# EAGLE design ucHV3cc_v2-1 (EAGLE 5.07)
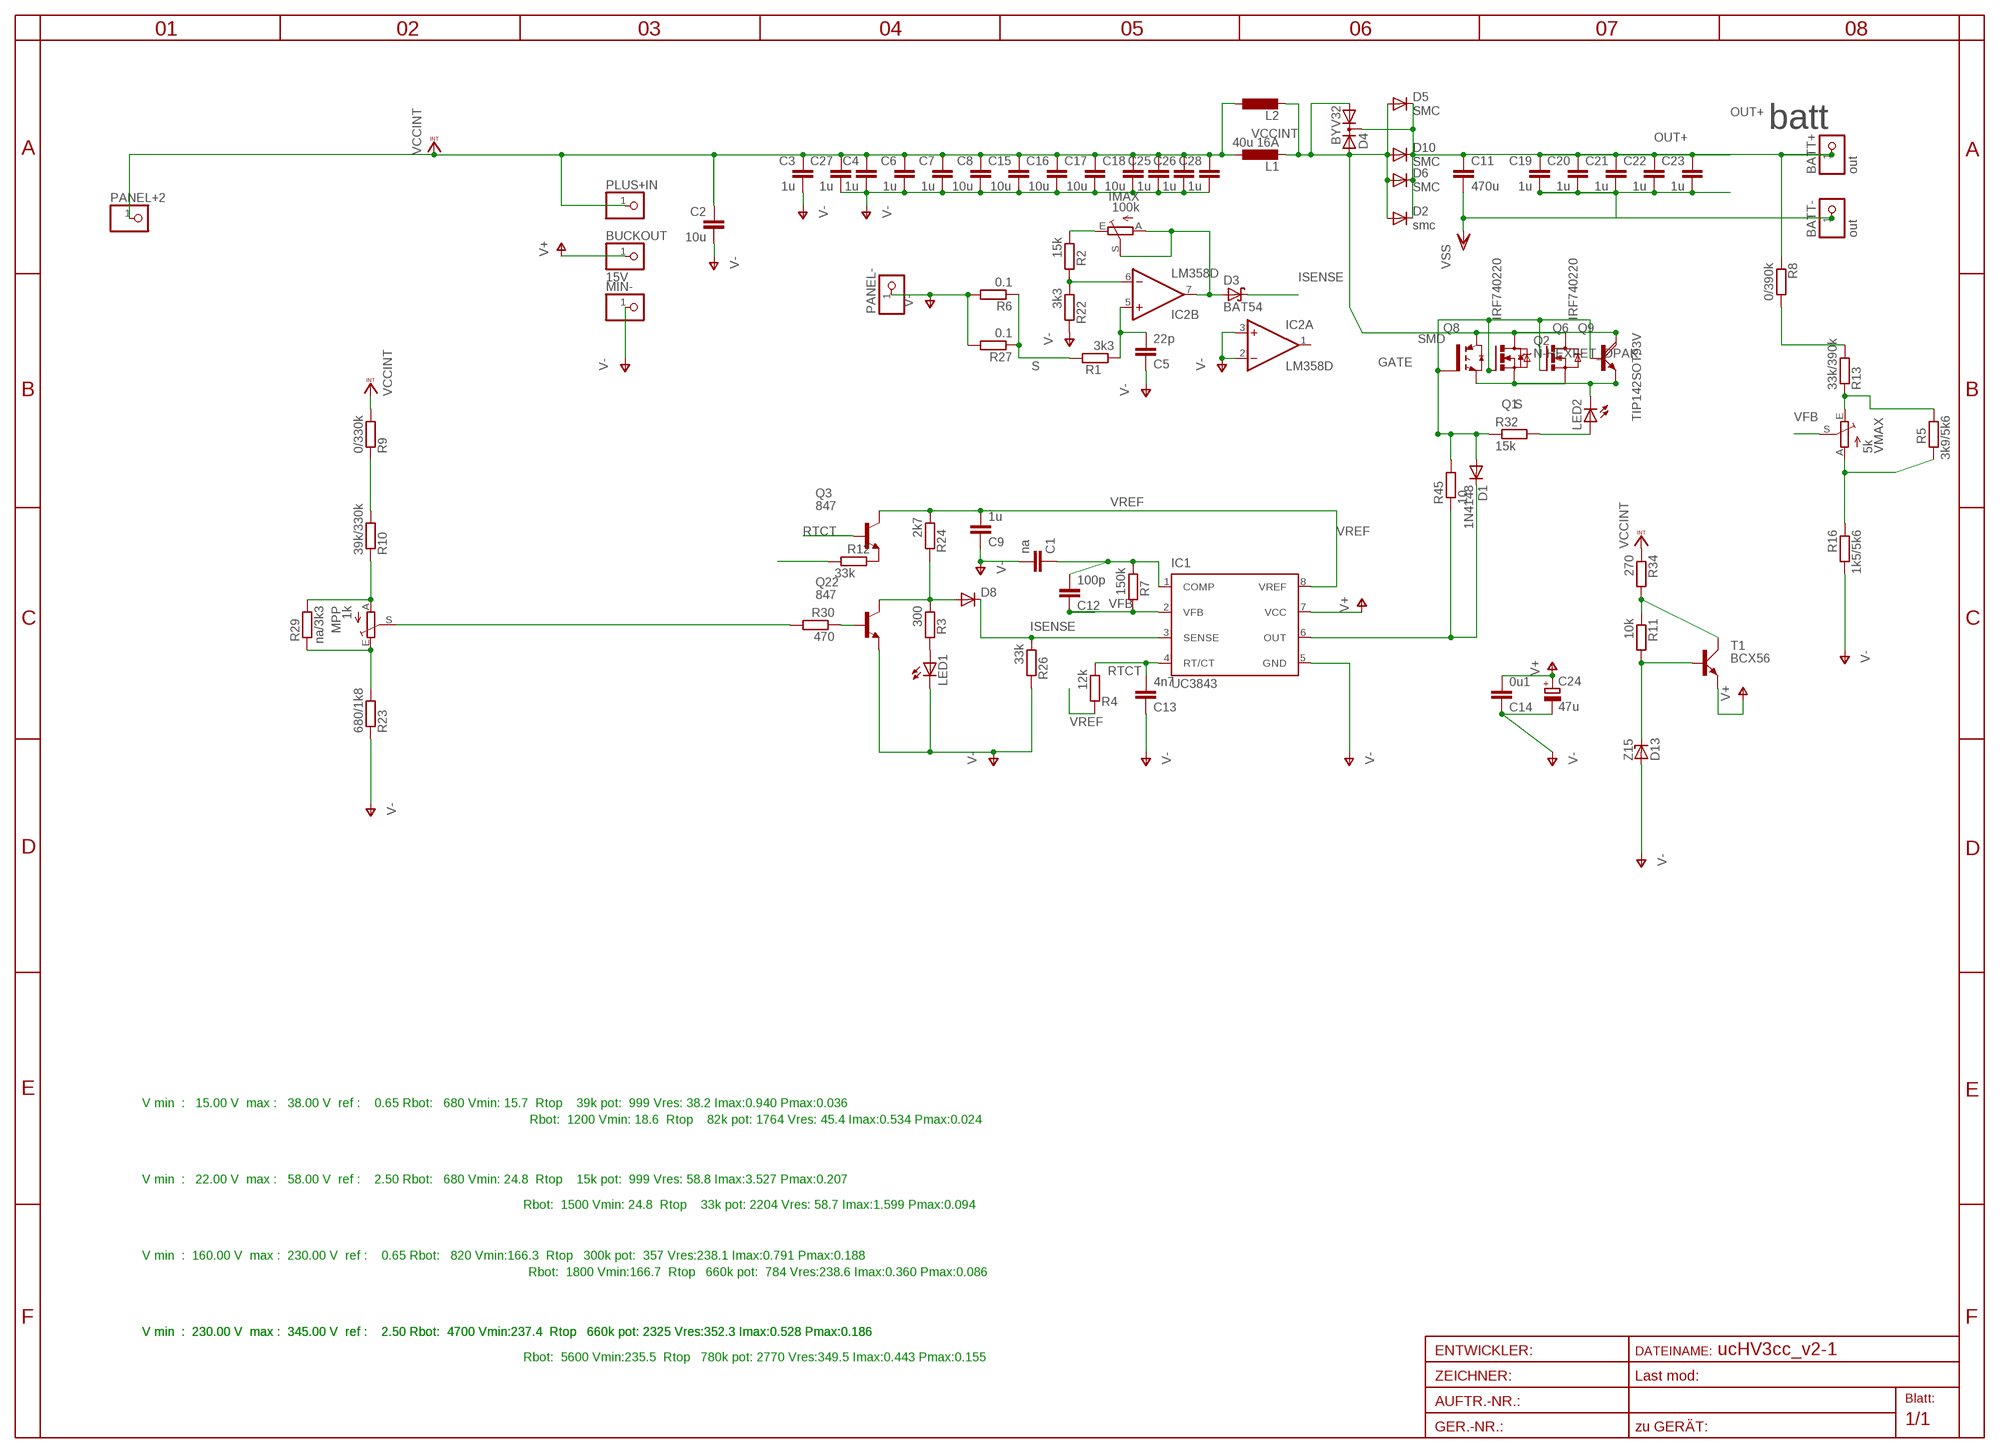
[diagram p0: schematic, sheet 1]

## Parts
BATT+  out  PINHD-1X12MM2  [1X2MM2]
BATT-  out  PINHD-1X12MM2  [1X2MM2]
BUCKOUT  15V  PINHD-1X11MM0  [1X1MM0]
C1  na  C-EUC0805  [C0805]
C2  10u  C-EUC058MLCC  [C058-020X040]
C3  1u  C-EUC058MLCC  [C058-020X040]
C4  1u  C-EUC058MLCC  [C058-020X040]
C5  22p  C-EUC0805  [C0805]
C6  1u  C-EUC058MLCC  [C058-020X040]
C7  1u  C-EUC058MLCC  [C058-020X040]
C8  10u  C-EUC058MLCC  [C058-020X040]
C9  1u  C-EUC1206  [C1206]
C11  470u  C-EU075-052X106  [C075-052X106]
C12  100p  C-EUC0805  [C0805]
C13  4n7  C-EUC0805  [C0805]
C14  0u1  C-EUC1206  [C1206]
C15  10u  C-EUC058MLCC  [C058-020X040]
C16  10u  C-EUC058MLCC  [C058-020X040]
C17  10u  C-EUC058MLCC  [C058-020X040]
C18  10u  C-EUC058MLCC  [C058-020X040]
C19  1u  C-EUC1206  [C1206]
C20  1u  C-EUC1206  [C1206]
C21  1u  C-EUC1206  [C1206]
C22  1u  C-EUC1206  [C1206]
C23  1u  C-EUC1206  [C1206]
C24  47u  CPOL-EUSANYO_SMD_C6  [SANYO-OSCON_SMD_C6]
C25  1u  C-EUC058MLCC  [C058-020X040]
C26  1u  C-EUC058MLCC  [C058-020X040]
C27  1u  C-EUC058MLCC  [C058-020X040]
C28  1u  C-EUC058MLCC  [C058-020X040]
D1  1N4148  DIODE-MINIMELF  [MINIMELF]
D2  smc  DIODE-SMC  [SMC]
D3  BAT54  [SOT23]
D4  BYV32  [TO220ABS]
D5  SMC  DIODE-SMC  [SMC]
D6  SMC  DIODE-SMC  [SMC]
D8  DIODE-SOT23  [SOT23]
D10  SMC  DIODE-SMC  [SMC]
D13  Z15  ZENER-DIODESOD80C  [SOD80C]
IC1  UC3843  UC1843D8  [SO-08]
IC2  LM358D  [SO08]
IMAX  100k  TRIM_EU-S64W  [S64W]
L1  40u 16A  L-EU  [RING]
L2  L-EUCEP125  [CEP125]
LED1  LEDCHIPLED_1206  [CHIPLED_1206]
LED2  LEDCHIPLED_1206  [CHIPLED_1206]
MIN-  PINHD-1X11MM0  [1X1MM0]
MPP  1k  TRIM_EU-S64W  [S64W]
PANEL+2  PINHD-1X11MM6  [1X1MM8]
PANEL-  PINHD-1X12MM2  [1X2MM2]
PLUS+IN  PINHD-1X11MM0  [1X1MM0]
Q1  IRF740220  [TO220BV]
Q2  N-HEXFET_DPAK-  [TO252]
Q3  847  BC847ASMD  [SOT23]
Q6  IRF740220  [TO220BV]
Q8  SMD  IRG4BC15UD-S  [D2PACK]
Q9  TIP142SOT93V  [SOT93V]
Q22  847  BC847ASMD  [SOT23]
R1  3k3  R-EU_R0805  [R0805]
R2  15k  R-EU_R0805  [R0805]
R3  300  R-EU_R0805  [R0805]
R4  12k  R-EU_R0805  [R0805]
R5  3k9/5k6  R-EU_R0805  [R0805]
R6  0.1  R-EU_0207/10  [0207/10]
R7  150k  R-EU_R0805  [R0805]
R8  0/390k  R-EU_R1206  [R1206]
R9  0/330k  R-EU_R1206  [R1206]
R10  39k/330k  R-EU_R1206  [R1206]
R11  10k  R-EU_R1206  [R1206]
R12  33k  R-EU_0207/10  [0207/10]
R13  33k/390k  R-EU_R1206  [R1206]
R16  1k5/5k6  R-EU_R0805  [R0805]
R22  3k3  R-EU_R0805  [R0805]
R23  680/1k8  R-EU_R0805  [R0805]
R24  2k7  R-EU_R0805  [R0805]
R26  33k  R-EU_R0805  [R0805]
R27  0.1  R-EU_R3216  [R3216]
R29  na/3k3  R-EU_R1203  [R1203]
R30  470  R-EU_R0805  [R0805]
R32  15k  R-EU_R0805  [R0805]
R34  270  R-EU_0617/17  [0617/17]
R45  10  R-EU_R0805  [R0805]
T1  BCX56  [SOT223]
VMAX  5k  TRIM_EU-S64W  [S64W]

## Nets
DQ18: D2.A D4.A1 D4.A2 D5.A D6.A D10.A L1.2 L2.2 Q1.D Q2.3(D) Q6.D Q8.2(C) Q9.C
GATE: D1.A Q1.G Q2.1(G) Q6.G Q8.1(G) Q9.B R32.1 R45.2
ISENSE: D3.3(C) D8.3(C) IC1.3(SENSE) R12.1 R26.1
N$1: C5.2 IC2.5(B:+IN) R1.1
N$2: IMAX.E R2.1
N$3: Q22.1(B) R30.1
N$4: LED1.A R3.2
N$5: LED2.A R32.2
N$6: R8.2 R13.2
N$7: D13.C R11.2 T1.1(B)
N$9: Q3.2(E) R12.2
N$18: C1.1 C12.2 IC1.1(COMP) R7.1
N$21: R5.2 R16.1 VMAX.A
N$22: D3.1(A) IC2.7(B:OUT) IMAX.A IMAX.S
N$23: R11.1 R34.2 T1.2(C)
N$25: D1.C IC1.6(OUT) R45.1
N$27: IC2.6(B:-IN) R2.2 R22.1
N$30: R9.1 R10.2
N$32: MPP.A R10.1 R29.1
N$34: MPP.E R23.2 R29.2
N$37: R5.1 R13.1 VMAX.E
N$71: D8.1(A) Q22.3(C) R3.1 R24.2
OUT+: BATT+.1 C11.1 C19.1 C20.1 C21.1 C22.1 C23.1 D2.C D4.C D5.C D6.C D10.C R8.1
PRB1: MPP.S R30.2
RTCT: C13.2 IC1.4(RT/CT) Q3.1(B) R4.1
S: LED2.C Q1.S Q2.2(S) Q6.S Q8.3(E) Q9.E R1.2 R6.1 R27.1
V+: BUCKOUT.1 C14.2 C24.+ IC1.7(VCC) T1.3(E)
V-: BATT-.1 C1.2 C2.2 C3.2 C4.2 C5.1 C6.2 C7.2 C8.2 C9.1 C11.2 C13.1 C14.1 C15.2 C16.2 C17.2 C18.2 C19.2 C20.2 C21.2 C22.2 C23.2 C24.- C25.2 C26.2 C27.2 C28.2 D13.A IC1.5(GND) IC2.2(A:-IN) IC2.3(A:+IN) LED1.C MIN-.1 PANEL-.1 Q22.2(E) R6.2 R16.2 R22.2 R23.1 R26.2 R27.2 ; supply symbol labelled VSS
VCCINT: C2.1 C3.1 C4.1 C6.1 C7.1 C8.1 C15.1 C16.1 C17.1 C18.1 C25.1 C26.1 C27.1 C28.1 L1.1 L2.1 PANEL+2.1 PLUS+IN.1 R9.2 R34.1
VFB: C12.1 IC1.2(VFB) R7.2 VMAX.S
VREF: C9.2 IC1.8(VREF) Q3.3(C) R4.2 R24.1
Unconnected: IC2.1(A:OUT)

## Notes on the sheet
- batt
- V min  :   15.00 V  max :   38.00 V  ref :    0.65 Rbot:   680 Vmin: 15.7  Rtop    39k pot:  999 Vres: 38.2 Imax:0.940 Pmax:0.036
- Rbot:  1200 Vmin: 18.6  Rtop    82k pot: 1764 Vres: 45.4 Imax:0.534 Pmax:0.024
- V min  :   22.00 V  max :   58.00 V  ref :    2.50 Rbot:   680 Vmin: 24.8  Rtop    15k pot:  999 Vres: 58.8 Imax:3.527 Pmax:0.207
- Rbot:  1500 Vmin: 24.8  Rtop    33k pot: 2204 Vres: 58.7 Imax:1.599 Pmax:0.094
- V min  :  160.00 V  max :  230.00 V  ref :    0.65 Rbot:   820 Vmin:166.3  Rtop   300k pot:  357 Vres:238.1 Imax:0.791 Pmax:0.188
- Rbot:  1800 Vmin:166.7  Rtop   660k pot:  784 Vres:238.6 Imax:0.360 Pmax:0.086
- V min  :  230.00 V  max :  345.00 V  ref :    2.50 Rbot:  4700 Vmin:237.4  Rtop   660k pot: 2325 Vres:352.3 Imax:0.528 Pmax:0.186 | V min  :  230.00 V  max :  345.00 V  ref :    2.50 Rbot:  4700 Vmin:237.4  Rtop   660k pot: 2325 Vres:352.3 Imax:0.528 Pmax:0.186
- Rbot:  5600 Vmin:235.5  Rtop   780k pot: 2770 Vres:349.5 Imax:0.443 Pmax:0.155

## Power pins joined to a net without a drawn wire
V+: IC2.8(P:V+)
V-: IC2.4(P:V-)

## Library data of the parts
BATT+ BATT- BUCKOUT MIN- PANEL+2 PANEL- PLUS+IN = pinhead:PINHD-1X1: PIN HEADER
C1-C9 C11-C23 C25-C28 = rcl:C-EU: CAPACITOR, European symbol
C24 = rcl:CPOL-EU: POLARIZED CAPACITOR, European symbol
D1 D2 D5 D6 D8 D10 = diode:DIODE-: DIODE
D3 = diode:BAT54: Schottky Diodes
D4 = diode:BYV32: DIODE 2 x Si diode 200 V, 20 A/230 Apeak, 25 ns
D13 = diode:ZENER-DIODE: Z-Diode
IC1 = texas:UC1843D8: PULSE WIDTH MODULATOR
IC2 = linear:LM358: OP AMP also LM158; LM258; LM2904 Source: http://cache.national.com/ds/LM/LM158.pdf
IMAX MPP VMAX = pot:TRIM_EU-: POTENTIOMETER
L1 L2 = rcl:L-EU: INDUCTOR, European symbol
LED1 LED2 = led:LED: LED
Q1 Q6 = transistor-power:IRF740: N-CHANNEL MOS FET
Q2 = transistor-power:N-HEXFET_?-*: HEXFET® Power MOSFET
Q3 Q22 = transistor-npn:BC847*: NPN Transistor
Q8 = transistor-power:IRG4BC15UD-: INSULATED GATE BIPOLAR TRANSISTOR WITH ULTRAFAST SOFT RECOVERY DIODE
Q9 = transistor-power:TIP142: NPN DARLINGTON TRANSISTOR
R1-R10 R12 R13 R16 R22-R24 R26 R27 R29 R30 R34 = rcl:R-EU_: RESISTOR, European symbol
R11 R32 R45 = rcl-2:R-EU_: RESISTOR, European symbol
T1 = transistor-power:BCX56

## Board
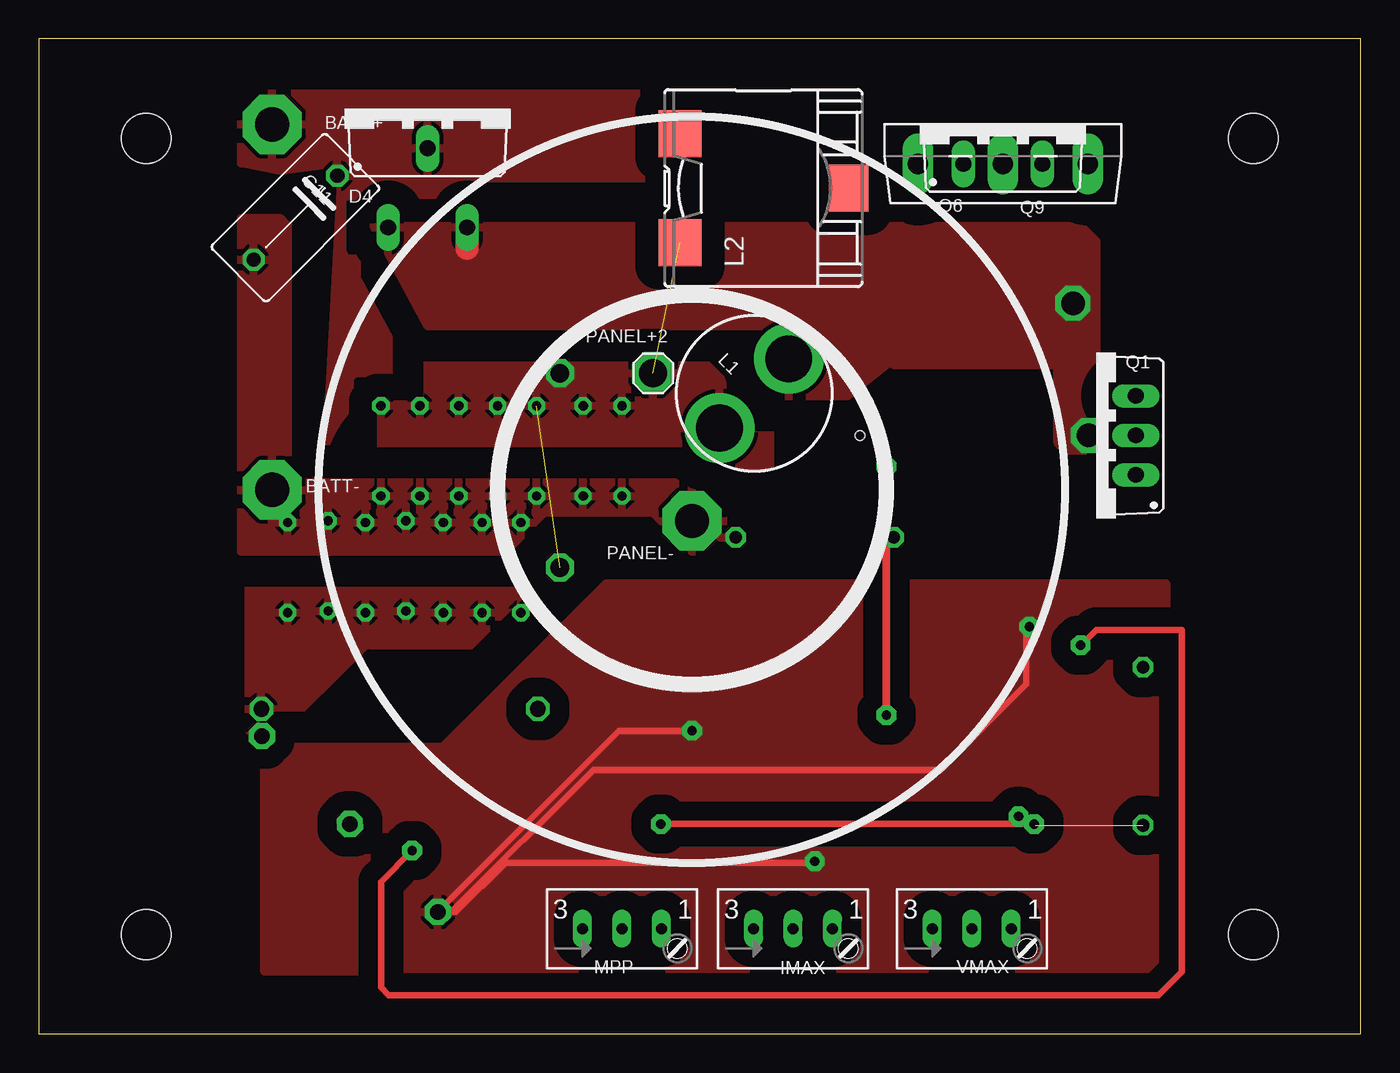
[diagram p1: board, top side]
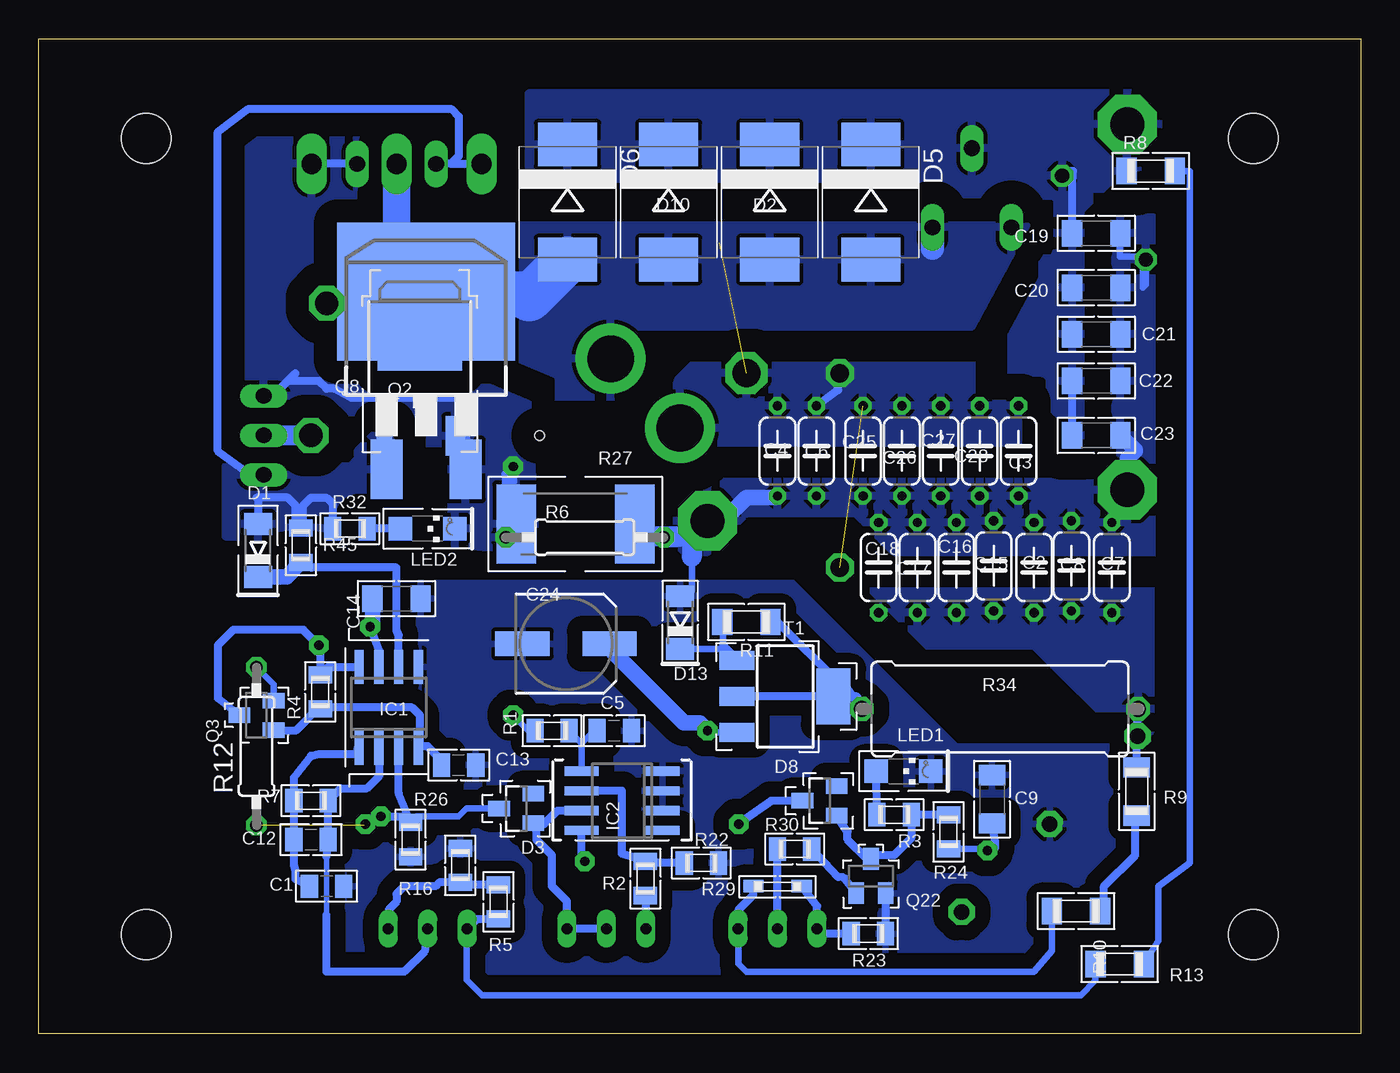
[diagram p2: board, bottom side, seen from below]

Size 85 x 64 mm. Coordinates in mm from the lower left corner, seen from the top.
Outline: 0,0 85,0 85,64 0,64 0,0
Copper layers (1*16): Top 0.035mm / dielectric 1.5mm / Bottom 0.035mm
Design rules "default *": minimum track width 10mil, minimum drill 24mil, track to track 8mil, track to pad 8mil, pad to pad 8mil, via to via 8mil, smd to smd 8mil, copper to edge 1mm, drill to drill 8mil, minimum pad ring 10mil, minimum via ring 8mil, stop-mask expansion 4mil, vias tented up to drill 0mil, thermal gap 10mil
Holes 3.2 mm at 6.9,57.6 6.9,6.4 78.1,6.4 78.1,57.6
Holes 0.6 mm at 52.8,38.5

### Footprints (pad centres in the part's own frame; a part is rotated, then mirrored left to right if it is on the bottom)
1X2MM2 = drill 2.2 pad 3.81 octagon: 1 0,0
1X1MM0 = drill 1 pad 1.676 octagon: 1 0,0
C0805 = smd 1.1 x 1.5: 1 -1.1,0; 2 1.1,0
C058-020X040 = drill 0.6 octagon: 1 -2.9,0; 2 2.9,0
C1206 = smd 1.3 x 1.7: 1 -1.55,0; 2 1.55,0
C075-052X106 = drill 0.914 octagon: 1 -3.81,0; 2 3.81,0
SANYO-OSCON_SMD_C6 = smd 3.5 x 1.6: + 2.8,0; - -2.8,0
MINIMELF = smd 1.4 x 1.8: A 1.7,0; C -1.7,0
SMC = smd 2.8 x 3.8: A 3.7,0; C -3.7,0
SOT23 = smd 1 x 1.4: 1 -0.95,-1.1; 2 0.95,-1.1; 3 0,1.1
TO220ABS = drill 1.016 long: A1 -2.54,-7.62; A2 2.54,-7.62; C 0,-2.54
SOD80C = smd 1.4 x 1.8: A 1.7,0; C -1.7,0
SO-08 = smd 0.6 x 2.2: 1 -1.905,-2.6; 2 -0.635,-2.6; 3 0.635,-2.6; 4 1.905,-2.6; 5 1.905,2.6; 6 0.635,2.6; 7 -0.635,2.6; 8 -1.905,2.6
SO08 = smd 0.6 x 2.2: 1 -1.905,-2.6; 2 -0.635,-2.6; 3 0.635,-2.6; 4 1.905,-2.6; 5 1.905,2.6; 6 0.635,2.6; 7 -0.635,2.6; 8 -1.905,2.6
S64W = drill 0.7 long: A 2.54,1.27; E -2.54,1.27; S 0,1.27
RING = drill 3 pad 4 round: 1 -3.15,0; 2 3.15,0
CEP125 = smd 3 x 2.75: 1 -3.5,5.375; 2 3.5,5.375 | smd 3 x 2.55: 3 0,-5.48
CHIPLED_1206 = smd 1.5 x 1.5: A 0,-1.75; C 0,1.75
1X1MM8 = drill 1.8 pad 2.54 octagon: 1 0,0
TO220BV = drill 1.016 long: D 0,-2.54; G -2.54,-2.54; S 2.54,-2.54
TO252 = smd 1 x 1.6: 1 -2.28,-3.53 | smd 1.27 x 2.54: 2 2.28,-3.53 | smd 5.4 x 6.2: 3 0,3.77
D2PACK = smd 2.083 x 3.81: 1 -2.54,-8.89; 3 2.54,-8.89 | smd 11.43 x 8.89: 2 0,2.54
SOT93V = drill 1.3 pad 1.676 long: B -5.461,-2.54; C 0,-2.54; E 5.461,-2.54
R0805 = smd 1.1 x 1.5: 1 -1.1,0; 2 1.1,0
0207/10 = drill 0.813 octagon: 1 -5.08,0; 2 5.08,0
R1206 = smd 1.3 x 1.7: 1 -1.55,0; 2 1.55,0
R3216 = smd 2.54 x 5.08: 1 -3.81,0; 2 3.81,0
R1203 = smd 1.3 x 0.8: 1 -1.55,0; 2 1.55,0
0617/17 = drill 1.016 octagon: 1 -8.89,0; 2 8.89,0
SOT223 = smd 1.219 x 2.235: 1 -2.311,-3.099; 2 0,-3.099; 3 2.311,-3.099 | smd 3.6 x 2.2: 4 0,3.099

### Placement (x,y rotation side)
BATT+  15,58.5 0 top
BATT-  15,35 0 top
BUCKOUT  25.66,7.84 90 top
C1  66.5,9.5 0 bottom
C2  21,30 90 bottom
C3  22,37.5 270 bottom
C4  37.5,37.5 270 bottom
C5  48,19.5 180 bottom
C6  35,37.5 270 bottom
C7  16,30 90 bottom
C8  18.6,30.1 90 bottom
C9  23.7,15.1 270 bottom
C11  16.5,52.5 225 top
C12  67.5,12.5 180 bottom
C13  58,17.3 180 bottom
C14  62,28 180 bottom
C15  23.6,30.1 90 bottom
C16  26,30 90 bottom
C17  28.5,30 90 bottom
C18  31,30 90 bottom
C19  17,51.5 0 bottom
C20  17,48 0 bottom
C21  17,45 0 bottom
C22  17,42 0 bottom
C23  17,38.5 0 bottom
C24  51.1,25.1 0 bottom
C25  32,37.5 270 bottom
C26  29.5,37.5 270 bottom
C27  27,37.5 270 bottom
C28  24.5,37.5 270 bottom
D1  70.9,31.1 90 bottom
D2  38,53.5 270 bottom
D3  54.3,14.5 90 bottom
D4  25,59.5 0 top
D5  31.5,53.5 270 bottom
D6  51,53.5 270 bottom
D8  34.8,15 90 bottom
D10  44.5,53.5 270 bottom
D13  43.76,26.46 90 bottom
IC1  62.5,21 0 bottom
IC2  47.5,15 90 bottom
IMAX  48.5,5.5 0 top
L1  46,41.2 45 top
L2  46.6,54.4 90 top
LED1  29.4,16.9 270 bottom
LED2  60,32.5 270 bottom
MIN-  20,13.5 315.7 top
MPP  37.5,5.5 0 top
PANEL+2  39.5,42.5 0 top
PANEL-  42,33 90 top
PLUS+IN  14.34,19.16 90 top
Q1  68,38.5 90 top
Q2  60.5,42 0 bottom
Q3  71,20.5 90 bottom
Q6  62,58.5 0 top
Q8  60.1,45.2 0 bottom
Q9  62,58.5 0 top
Q22  31.49,10.16 0 bottom
R1  52,19.5 180 bottom
R2  46,10 90 bottom
R3  30,14.1 180 bottom
R4  66.9,22 90 bottom
R5  55.45,8.5 90 bottom
R6  49.9,31.95 0 bottom
R7  67.5,15 0 bottom
R8  13.5,55.5 0 bottom
R9  14.4,15.6 90 bottom
R10  18.3,7.9 0 bottom
R11  39.5,26.5 180 bottom
R12  71,18.5 90 bottom
R13  15.5,4.5 0 bottom
R16  57.9,10.85 90 bottom
R22  42.4,11 0 bottom
R23  31.66,6.46 180 bottom
R24  26.5,13 90 bottom
R26  61.1,12.5 270 bottom
R27  50.5,32.8 0 bottom
R29  37.5,9.5 0 bottom
R30  36.4,11.9 180 bottom
R32  65,32.5 0 bottom
R34  23.2,20.9 180 bottom
R45  68.15,31.43 90 bottom
T1  37,21.7 270 bottom
VMAX  60,5.5 0 top

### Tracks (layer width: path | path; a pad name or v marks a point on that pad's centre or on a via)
DQ18  (via drill 1.5 pad 1.2)
  Top 1.5: 27.54,50.54 D4.A2
  Bottom 0.406: v66.5,47 61.4,47 61.4,47.89
  Bottom 0.5: Q2.3 60.5,46.1 61.4,47
  Bottom 1.27: v67.5,38.5 Q1.D
  Bottom 1.5: D4.A2 27.54,50.54
  Bottom 1.778: 62,48.04 Q9.C
  Bottom 2.54: Q8.2 61.4,47.89 62,48.04
  Bottom 3: Q8.2 53.54,47.54 53.47,47.34 D6.A
  pour Bottom (isolate 1.5, rank 2): 21.5,52 55.5,52 54.5,43 52,41 47,41 47,45.5 25,45.5
  pour Top (isolate 2): 54.5,52 67,52 68,51 68,38 67.5,37.5 66,37.5 65.5,38 65.5,43 55,43 54.5,43.5
  pour Top (isolate 1.5, rank 2): 21.5,52 55.5,52 54.5,43 52,41 47,41 47,45.5 25,45.5
GATE
  Bottom 0.406: Q1.G 71,36.46 71,36.11
  Bottom 0.5: 58.5,55.96 Q9.B | 58.5,55.96 Q6.G | 71,36.11 71.61,36.11 73.5,37.5 73.5,58 71.5,59.5 58.5,59.5 58,59 58,56.46 58.5,55.96 | Q8.1 62.64,38.33 Q2.1 | R32.1 66.1,34.1 66.5,34.5 67.5,34.5 68,34 68,32.68 R45.2 68.03,32.53 | D1.A 70.9,34.4 71,34.5 69,34.5 68.5,34 68.5,33 68.03,32.53 | 68.03,32.53 68,32.5
  pour Bottom (isolate 1.5): 62.5,38.5 63.5,38.5 64.5,37.5 64.5,37 65,36.5 73,36.5 73,32 66,32 65.5,32.5 65.5,33 63.5,35 62,35 62,37.5
ISENSE  (via drill 0.6 pad 1.27)  (1 unrouted)
  Top 0.406: v40,13.5 v64,13.5
  Top 1: v64,13.5 64.08,13.42
  Bottom 0.406: v63,14 63.5,14 v64,13.5 | D3.3 57.5,14.5 58,14 60.7,14 R26.1
  Bottom 0.5: IC1.3 61.87,15.46 R26.1 61.5,14 v63,14 | D8.3 37.9,15 v40,13.5
N$1
  Bottom 0.406: IC2.5 50.1,18.7 | 50.1,18.7 R1.1 | C5.2 49.3,19.5 50.1,18.7
N$2
  Bottom 0.5: IMAX.E 45.96,8.86 R2.1
N$3
  Bottom 0.5: Q22.1 33.26,10.06 33.6,10.1 R30.1
N$4
  Bottom 0.5: R3.2 LED1.A
N$5
  Bottom 0.5: LED2.A R32.2
N$6
  Bottom 0.406: R8.2 11,55.5 11,11 13,9.5 13,6 R13.2
N$7
  Bottom 0.406: D13.C 40.84,24.76 T1.1 | 41,25 41,26.45
  Bottom 0.5: T1.1 40.1,24.1 41,25 | 41,26.45 R11.2
N$9
  Bottom 0.406: Q3.2 69.9,22.48 R12.2
N$18
  Bottom 0.5: C1.1 68.5,9.95 68.5,10.5 68.6,10.9 C12.2 R7.1 68.6,16.5 67.5,17.9 67,18 64.5,18 64.5,18.4 IC1.1
N$21
  Bottom 0.5: R5.2 57.75,9.6 R16.1 59.25,9.75 59.5,9.5 61.5,9.5 62,9 62,8.5 62.5,8 62.5,6.81 VMAX.A
N$22
  Bottom 0.5: IMAX.S IMAX.A 51.04,8.54 52,9.5 52,11.5 53,12.5 53,13.45 D3.1 52.85,13.5 52.5,13.5 51.63,14.37 IC2.7
N$23
  Bottom 0.5: T1.2 32.39,21.7 R34.2 33.19,22.5 33.5,22.5 37.5,26.5 R11.1
N$25
  Bottom 0.5: IC1.6 61.87,25.64 62,26 62,30 67.48,30 R45.1
  Bottom 1: D1.C 69.08,29.4 R45.1
N$27
  Bottom 0.5: IC2.6 47.5,15.63 47.5,11.6 R2.2 45.9,11 R22.1
N$30
  Bottom 0.5: R10.2 16.5,8 16.5,9.5 14.5,11.5 14.5,14.05 R9.1
N$32
  Bottom 0.406: 40.04,7.04 MPP.A 40,6.73 40,4.5 39.5,4 21,4 19.85,5.35 R10.1
  Bottom 0.5: R29.1 39.05,8.95 40,8 40,6.81 MPP.A
N$34
  Bottom 0.5: R23.2 34.77,6.46 MPP.E 34.96,8.21 R29.2
N$37
  Top 0.5: VMAX.E 57.5,6.73
  Bottom 0.406: R13.1 17.05,3.45 18,2.5 56.5,2.5 57.5,3.5 57.5,6.73 VMAX.E
  Bottom 0.5: 57.4,6.83 VMAX.E 56.83,7.4 R5.1
N$71
  Bottom 0.5: R24.2 R3.1 28.9,12.6 30,11.5 31.25,11.5 Q22.3 31.76,11.26 33,12.5 33,13 D8.1
OUT+
  Bottom 0.5: C23.1 C22.1 | C19.1 18.55,54.45 18.5,55.5 18.89,55.5 C11.1
  pour Bottom (isolate 1.5, rank 4): 13,56 13,60.5 53.5,60.5 53.5,55 28.5,55 22.5,51 22.5,42 arc46 18,37.5 18,53 15.5,55.5
  pour Top (isolate 1.5, rank 4): 13,56 13,60.5 48.5,60.5 48.5,55 28.5,55 22.5,51 22.5,42 arc46 18.5,38 19.5,56 15.5,55.5
PRB1
  Bottom 0.5: MPP.S R30.2
RTCT
  Bottom 0.406: 69.35,19.5 Q3.1
  Bottom 0.5: 67,21 R4.1 | 67,21 61,21 60.5,20.5 60.5,18.5 IC1.4 60.49,18.5 60,18.5 59.1,17.6 C13.2 | 67,21 68.5,19.5 69.35,19.5
S  (via drill 0.6 pad 1.27)
  Top 0.5: v54.5,20.5 v54.5,36.5
  Bottom 0.406: R1.2 53.5,19.5 v54.5,20.5
  Bottom 0.5: Q6.S Q9.E | 57.11,36.11 Q8.3 57.5,36.37 57.5,40 57.9,40.9 64.9,40.9 66,41.5 66.5,41.5 67,42 69,42 | Q1.S 69.46,41.54 69,42 | 69,42 68.5,42.5 | v54.5,36.5 54.5,35.5 55,36 55,31.97 R6.1
  Bottom 1.27: R6.1 54.31,31.95 R27.1
  pour Bottom (isolate 1.5): 64.5,58 73,58 73.5,57.5 73.5,39 72,39 71,40 65,40 63,38 58.5,38 58.5,31.5 53,31 53.5,40.5 57,42 65,42 65.5,42.5
V+  (via drill 0.6 pad 1.27)
  Top 0.406: 26.5,7.84 BUCKOUT.1 37.31,19.5 v42,19.5 | 26.5,7.84 26.84,7.84 30,11 49.8,11 v49.9,11.1 | v63.7,26.2 63.5,26 63.5,22.5 58,17 35.66,17 26.5,7.84
  Bottom 0.406: 42,19.39 T1.3 | 48.1,24.6 C24.+
  Bottom 0.5: IC1.7 63.13,24.66 v63.7,26.2 | IC2.8 50.1,11.4 v49.9,11.1
  Bottom 1: 42,19.39 v42,19.5 42.5,20 43.5,20 48.1,24.6 | C14.2 63.55,26.35 v63.7,26.2
  pour Top (isolate 1.25): 36.5,29 72.5,29 72.5,4 14.5,4 14.5,18.5 26,18.5
V-
  Bottom 0.406: 43,30.7 43,28.5 43.71,28.5 D13.A | C11.2 13.81,48.19 14,48 14,50 15.5,50 15.5,51.45 C19.2
  Bottom 0.5: R23.1 30.5,6.5 30.5,6 30.54,6.97 Q22.2
  Bottom 1: PANEL-.1 41,33 39.5,34.5 37.6,34.5 C4.2 | BATT-.1 15,37 14.5,37.5 14.5,37.55 C23.2
  Bottom 1.27: PANEL-.1 43,32 | 43,32 43,30.7 | 43,32 43.5,32 | 43.5,32 46.69,32 R27.2 | R6.2 44,31.95 43.5,32
  pour Bottom (isolate 1): 36.5,29 72.5,29 72.5,4 14.5,4 14.5,18.5 26,18.5
  pour Bottom (isolate 2): 13,52.5 15.5,52.5 16,52 16,35.5 44,35.5 44,31.5 43.5,31 42,31 39.5,33.5 32.5,33.5 30,31 13,31
  pour Top (isolate 2): 13,52.5 15.5,52.5 16,52 16,35.5 44,35.5 44,31.5 43.5,31 42,31 39.5,33.5 32.5,33.5 30,31 13,31
VCCINT  (via drill 1.2)  (2 unrouted)
  Bottom 0.5: R34.1 14.34,21.37 PLUS+IN.1 14.4,19.1 R9.2 | C6.1 33.6,41.4 v33.5,42.5
  other vias: 33.5,30
  pour Bottom (isolate 2, rank 2): 13.5,29 30,29 33,32.5 40,32.5 40,30 36.5,30 31.5,25 21,25 15,19 14,19 13.5,19.5
  pour Bottom (isolate 2, rank 3): 25,43.5 42.5,43.5 47,39 47,36.5 39.5,36.5 39,37 22,37.5 22,40.5 25,40.5
  pour Top (isolate 2, rank 2): 13.5,29 30,29 33,32.5 40,32.5 40,30 36.5,30 31.5,25 21,25 15,19 14,19 13.5,19.5
  pour Top (isolate 2, rank 3): 25,43.5 42.5,43.5 47,39 47,36.5 39.5,36.5 39,37 22,37.5 22,40.5 25,40.5
VFB
  Bottom 0.35: 66.5,7.63 66.5,11.4
  Bottom 0.5: VMAX.S 60.2,5.29 61.5,4 66.5,4 66.5,7.63 | 66.5,11.4 66.4,12.16 C12.1 R7.2 65.6,15.8 63.9,15.8 63.1,16.6 63.1,17.36 IC1.2
VREF  (via drill 0.6 pad 1.27)
  Top 0.406: v67,25 68,26 73.5,26 73.5,4 72,2.5 22.5,2.5 22,3 22,9.8 v24,11.8
  Bottom 0.406: R24.1 23.6,11.9 23.5,12
  Bottom 0.5: IC1.8 66.4,23.6 R4.2 66.9,24.4 67,24.5 v67,25 68,26 72.5,26 73.5,25 73.5,21.6 Q3.3 | v24,11.8 23.5,12 23.5,12.35 C9.2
